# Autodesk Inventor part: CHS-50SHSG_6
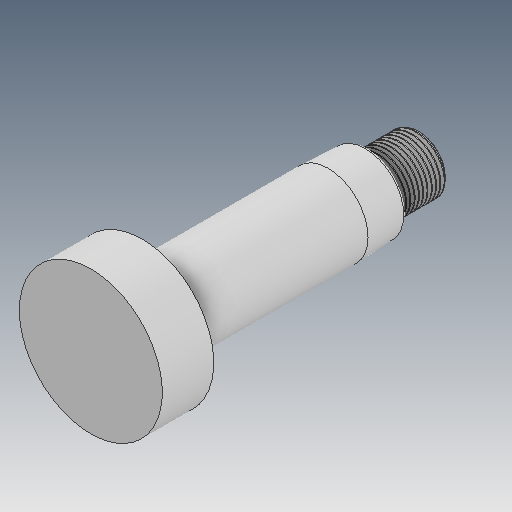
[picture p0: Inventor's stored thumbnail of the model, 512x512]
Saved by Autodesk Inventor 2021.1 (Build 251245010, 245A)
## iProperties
Created: 2019-04
Part Number: CHS-50SHSG_6
Material: Ogólny
Document SubType Name: Modeling
Designer: user
Density: 1 g/cm^3
Appearance: Domyślna
Author: user
Revision Number: ÈÎºÎ
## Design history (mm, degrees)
feature "ÊäÈë1"
node "Bryła1"
